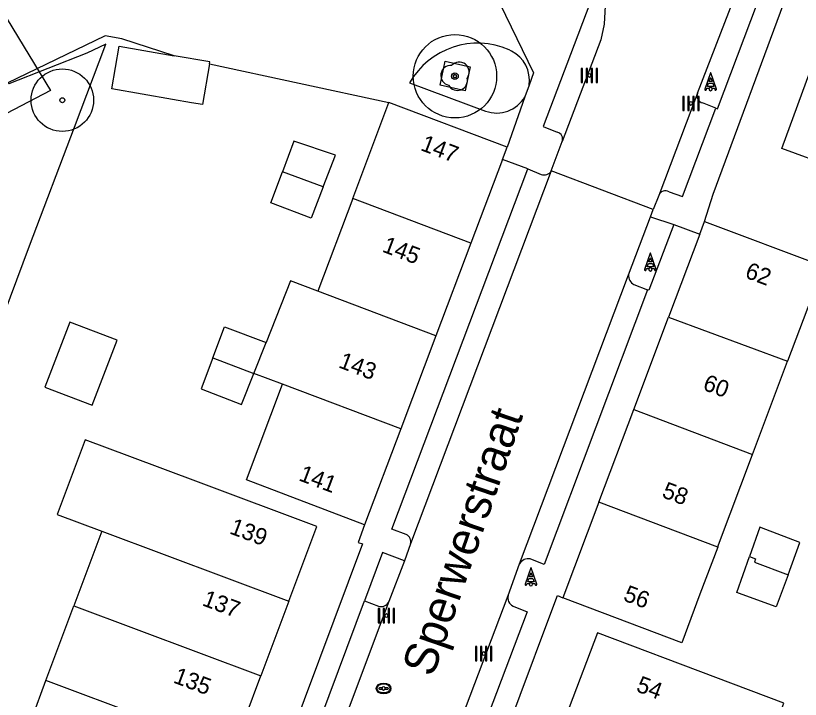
# Model space of a CAD drawing. Extents: x 192664 to 192925, y 446334 to 446521.
# Drawn here: x 192738.2 to 192785.27, y 446453.47 to 446494.45 of the extents above; entities that cross this region are included whole.
import ezdxf

# ---------------------------------------------------------------- set-up
doc = ezdxf.new("R2010")
doc.units = 0
for name, color, linetype in [('( Toegevoegd 29-11-2021 14_41_42) wegdeel vlak', 7, 'Continuous'), ('B-GV-GR-BOOM-S', 7, 'Continuous'), ('B-GV-KG-GRENS_WERKGRENS-G', 7, 'Continuous'), ('boom', 7, 'Continuous'), ('bovenleidingmast', 7, 'Continuous'), ('grens maaiveld', 7, 'Continuous'), ('huisnummerreeks BGT', 7, 'Continuous'), ('inspectie-   rioolput', 7, 'Continuous'), ('kant open verharding', 7, 'Continuous'), ('kant verharding', 7, 'Continuous'), ('kolk', 7, 'Continuous'), ('pand op maaiveld vlak', 7, 'Continuous'), ('straatnaam', 7, 'Continuous'), ('verkeerseiland - berm', 7, 'Continuous')]:
    doc.layers.add(name, color=color, linetype=linetype)

msp = doc.modelspace()

# ---------------------------------------------------------------- linework, layer by layer
at = {"layer": '( Toegevoegd 29-11-2021 14_41_42) wegdeel vlak'}
msp.add_line((192749.833, 446491.572), (192760.593, 446489.25), dxfattribs=at)
msp.add_lwpolyline([(192747.709, 446492.058), (192744.573, 446493.06), (192743.573, 446493.255), (192737.693, 446490.405)], dxfattribs=at)
at = {"layer": 'B-GV-GR-BOOM-S'}
for centre, radius in [((192764.55, 446490.826), 2.5), ((192740.997, 446489.39), 1.875), ((192764.55, 446490.826), 0.2), ((192740.997, 446489.39), 0.15)]:
    msp.add_circle(centre, radius, dxfattribs=at)
at = {"layer": 'B-GV-KG-GRENS_WERKGRENS-G'}
msp.add_lwpolyline([(192740.295, 446489.973), (192734.557, 446486.987), (192730.473, 446485.129), (192725.366, 446482.882), (192721.029, 446481.333), (192717.923, 446480.635), (192713.732, 446480.061), (192710.196, 446479.993), (192707.335, 446480.383), (192700.156, 446483.797), (192705.941, 446486.582), (192708.78, 446485.232), (192710.487, 446485), (192713.343, 446485.054), (192717.034, 446485.56), (192719.635, 446486.145), (192723.516, 446487.53), (192728.43, 446489.693), (192732.367, 446491.484), (192737.694, 446494.256)], close=True, dxfattribs=at)
at = {"layer": 'boom'}
msp.add_circle((192764.55, 446490.826), 0.1, dxfattribs=at)
for centre, radius, start, end in [((192764.3, 446490.876), 0.6, 85.137, 257.7544), ((192764.8, 446491.076), 0.6, 323.5446, 138.4658), ((192764.55, 446490.826), 0.1, 0, 180), ((192764.7, 446490.576), 0.6, 208.5058, 13.8356), ((192764.55, 446490.826), 0.1, 180, 0)]:
    msp.add_arc(centre, radius, start, end, dxfattribs=at)
at = {"layer": 'bovenleidingmast'}
for p, q in [((192779.881, 446491.025), (192779.54, 446490.052)), ((192780.24, 446490.052), (192779.899, 446491.025)), ((192776.265, 446480.215), (192775.924, 446479.242)), ((192776.624, 446479.242), (192776.283, 446480.215)), ((192769.099, 446461.346), (192768.758, 446460.373)), ((192769.458, 446460.373), (192769.117, 446461.346))]:
    msp.add_line(p, q, dxfattribs=at)
for points in [[(192779.899, 446490.722), (192779.977, 446490.502), (192779.803, 446490.502), (192779.881, 446490.722)], [(192779.634, 446490.019), (192779.663, 446490.102), (192779.803, 446490.102)], [(192779.977, 446490.102), (192780.117, 446490.102), (192780.146, 446490.019)], [(192776.283, 446479.912), (192776.361, 446479.692), (192776.187, 446479.692), (192776.265, 446479.912)], [(192776.018, 446479.209), (192776.047, 446479.292), (192776.187, 446479.292)], [(192776.361, 446479.292), (192776.501, 446479.292), (192776.53, 446479.209)], [(192769.117, 446461.043), (192769.195, 446460.823), (192769.021, 446460.823), (192769.099, 446461.043)], [(192768.852, 446460.34), (192768.881, 446460.423), (192769.021, 446460.423)], [(192769.195, 446460.423), (192769.335, 446460.423), (192769.364, 446460.34)]]:
    msp.add_lwpolyline(points, dxfattribs=at)
for points in [[(192780.012, 446490.402), (192780.082, 446490.202), (192779.698, 446490.202), (192779.768, 446490.402)], [(192776.396, 446479.592), (192776.466, 446479.392), (192776.082, 446479.392), (192776.152, 446479.592)], [(192769.23, 446460.723), (192769.3, 446460.523), (192768.916, 446460.523), (192768.986, 446460.723)]]:
    msp.add_lwpolyline(points, close=True, dxfattribs=at)
for centre, radius, start, end in [((192779.89, 446491.022), 0.01, 19.29, 160.71), ((192779.89, 446490.719), 0.01, 19.29, 160.71), ((192779.587, 446490.035), 0.05, 160.71, 340.71), ((192779.89, 446490.052), 0.1, 0, 180), ((192779.89, 446490.052), 0.1, 180, 0), ((192779.89, 446490.052), 0.1, 30, 150), ((192780.193, 446490.035), 0.05, 199.29, 19.29), ((192776.274, 446480.212), 0.01, 19.29, 160.71), ((192776.274, 446479.909), 0.01, 19.29, 160.71), ((192775.971, 446479.225), 0.05, 160.71, 340.71), ((192776.274, 446479.242), 0.1, 0, 180), ((192776.274, 446479.242), 0.1, 180, 0), ((192776.274, 446479.242), 0.1, 30, 150), ((192776.577, 446479.225), 0.05, 199.29, 19.29), ((192769.108, 446461.343), 0.01, 19.29, 160.71), ((192769.108, 446461.04), 0.01, 19.29, 160.71), ((192768.805, 446460.356), 0.05, 160.71, 340.71), ((192769.108, 446460.373), 0.1, 0, 180), ((192769.108, 446460.373), 0.1, 180, 0), ((192769.108, 446460.373), 0.1, 30, 150), ((192769.411, 446460.356), 0.05, 199.29, 19.29)]:
    msp.add_arc(centre, radius, start, end, dxfattribs=at)
at = {"layer": 'grens maaiveld'}
for p, q in [((192739.028, 446480.658), (192741.724, 446487.765)), ((192734.733, 446469.332), (192739.028, 446480.658))]:
    msp.add_line(p, q, dxfattribs=at)
msp.add_lwpolyline([(192741.724, 446487.765), (192743.611, 446492.741), (192742.468, 446492.211), (192737.789, 446490.36), (192737.693, 446490.405)], dxfattribs=at)
at = {"layer": 'inspectie-   rioolput'}
for p, q in [((192760.175, 446454.158), (192760.018, 446454.158)), ((192760.018, 446454.083), (192760.175, 446454.083)), ((192760.518, 446454.158), (192760.361, 446454.158)), ((192760.361, 446454.083), (192760.518, 446454.083))]:
    msp.add_line(p, q, dxfattribs=at)
for centre, radius, start, end in [((192760.268, 446454.12), 0.1, 0, 180), ((192760.018, 446454.12), 0.0375, 90, 270), ((192760.268, 446454.12), 0.1, 157.9757, 180), ((192760.268, 446454.12), 0.1, 180, 202.0243), ((192760.268, 446454.12), 0.1, 180, 0), ((192760.268, 446454.12), 0.1, 0, 22.0243), ((192760.268, 446454.12), 0.1, 337.9757, 0), ((192760.518, 446454.12), 0.0375, 270, 90)]:
    msp.add_arc(centre, radius, start, end, dxfattribs=at)
for major_axis, ratio in [((-0.442, 0), 0.73911), ((-0.392, 0), 0.689655)]:
    msp.add_ellipse((192760.268, 446454.12), major_axis=major_axis, ratio=ratio, dxfattribs=at)
at = {"layer": 'kant open verharding'}
for p, q in [((192768.751, 446489.598), (192767.686, 446486.569)), ((192770.332, 446485.145), (192770.985, 446486.905)), ((192768.919, 446485.267), (192767.41, 446485.838)), ((192776.448, 446482.826), (192770.332, 446485.145)), ((192776.776, 446483.684), (192776.448, 446482.826)), ((192777.672, 446481.946), (192779.24, 446481.355))]:
    msp.add_line(p, q, dxfattribs=at)
for points in [[(192779.53, 446482.124), (192780.051, 446483.746), (192784.415, 446495.597), (192785.528, 446497.018), (192791.864, 446500), (192801.451, 446504.762), (192802.996, 446505.531), (192810.052, 446508.944)], [(192765.561, 446498.667), (192769.255, 446491.03), (192768.995, 446490.291)], [(192759.131, 446463.938), (192758.744, 446462.881), (192758.998, 446462.784), (192748.571, 446434.902)], [(192761.515, 446461.771), (192760.208, 446462.264), (192759.133, 446459.368)], [(192763.131, 446439.452), (192770.245, 446458.483), (192770.698, 446459.694), (192771.023, 446459.551)]]:
    msp.add_lwpolyline(points, dxfattribs=at)
at = {"layer": 'kant verharding'}
for p, q in [((192779.096, 446489.802), (192776.776, 446483.684)), ((192768.919, 446485.267), (192769.718, 446484.933)), ((192770.332, 446485.145), (192761.884, 446462.784)), ((192776.287, 446482.406), (192776.448, 446482.826)), ((192768.431, 446461.589), (192774.955, 446478.925)), ((192761.884, 446462.784), (192761.515, 446461.771)), ((192761.515, 446461.771), (192760.585, 446459.343)), ((192767.733, 446459.699), (192768.431, 446461.589)), ((192759.42, 446437.63), (192767.733, 446459.699)), ((192751.413, 446438.852), (192759.133, 446459.368)), ((192760.585, 446459.343), (192752.554, 446437.93)), ((192759.133, 446459.368), (192759.958, 446459.051))]:
    msp.add_line(p, q, dxfattribs=at)
for points in [[(192777.392, 446483.905), (192778.209, 446483.619), (192780.204, 446488.916)], [(192761.621, 446463.349), (192760.755, 446463.677), (192768.919, 446485.267)], [(192776.11, 446478.029), (192769.909, 446461.548), (192769.066, 446461.885)], [(192768.035, 446459.06), (192768.878, 446458.723), (192760.872, 446437.554), (192760.052, 446437.884)]]:
    msp.add_lwpolyline(points, dxfattribs=at)
for centre, radius, start, end in [((192769.888, 446485.436), 0.531, 251.3114, 326.7858), ((192777.179, 446483.53), 0.431, 60.3638, 159.1088), ((192761.434, 446462.918), 0.47, 343.3869, 66.5358), ((192768.943, 446461.319), 0.579, 77.7905, 152.1938), ((192768.263, 446459.559), 0.548, 165.168, 245.4241), ((192760.116, 446459.532), 0.506, 251.8409, 338.1029)]:
    msp.add_arc(centre, radius, start, end, dxfattribs=at)
at = {"layer": 'kolk'}
for points in [[(192772.212, 446490.872), (192772.212, 446491.297), (192772.127, 446491.297), (192772.127, 446490.872), (192772.127, 446490.447), (192772.212, 446490.447)], [(192772.51, 446490.872), (192772.51, 446491.297), (192772.425, 446491.297), (192772.425, 446490.872), (192772.425, 446490.447), (192772.51, 446490.447)], [(192772.807, 446490.872), (192772.807, 446491.297), (192772.722, 446491.297), (192772.722, 446490.872), (192772.722, 446490.447), (192772.807, 446490.447)], [(192773.105, 446490.872), (192773.105, 446491.297), (192773.02, 446491.297), (192773.02, 446490.872), (192773.02, 446490.447), (192773.105, 446490.447)], [(192778.304, 446489.194), (192778.304, 446489.619), (192778.219, 446489.619), (192778.219, 446489.194), (192778.219, 446488.769), (192778.304, 446488.769)], [(192778.602, 446489.194), (192778.602, 446489.619), (192778.517, 446489.619), (192778.517, 446489.194), (192778.517, 446488.769), (192778.602, 446488.769)], [(192778.899, 446489.194), (192778.899, 446489.619), (192778.814, 446489.619), (192778.814, 446489.194), (192778.814, 446488.769), (192778.899, 446488.769)], [(192779.197, 446489.194), (192779.197, 446489.619), (192779.112, 446489.619), (192779.112, 446489.194), (192779.112, 446488.769), (192779.197, 446488.769)], [(192760.035, 446458.49), (192760.035, 446458.915), (192759.95, 446458.915), (192759.95, 446458.49), (192759.95, 446458.065), (192760.035, 446458.065)], [(192760.333, 446458.49), (192760.333, 446458.915), (192760.248, 446458.915), (192760.248, 446458.49), (192760.248, 446458.065), (192760.333, 446458.065)], [(192760.63, 446458.49), (192760.63, 446458.915), (192760.545, 446458.915), (192760.545, 446458.49), (192760.545, 446458.065), (192760.63, 446458.065)], [(192760.928, 446458.49), (192760.928, 446458.915), (192760.843, 446458.915), (192760.843, 446458.49), (192760.843, 446458.065), (192760.928, 446458.065)], [(192765.871, 446456.21), (192765.871, 446456.635), (192765.786, 446456.635), (192765.786, 446456.21), (192765.786, 446455.785), (192765.871, 446455.785)], [(192766.169, 446456.21), (192766.169, 446456.635), (192766.084, 446456.635), (192766.084, 446456.21), (192766.084, 446455.785), (192766.169, 446455.785)], [(192766.466, 446456.21), (192766.466, 446456.635), (192766.381, 446456.635), (192766.381, 446456.21), (192766.381, 446455.785), (192766.466, 446455.785)], [(192766.764, 446456.21), (192766.764, 446456.635), (192766.679, 446456.635), (192766.679, 446456.21), (192766.679, 446455.785), (192766.764, 446455.785)]]:
    msp.add_lwpolyline(points, close=True, dxfattribs=at)
for centre, start, end in [((192772.616, 446490.872), 0, 180), ((192772.616, 446490.872), 180, 0), ((192778.708, 446489.194), 0, 180), ((192778.708, 446489.194), 180, 0), ((192760.439, 446458.49), 0, 180), ((192760.439, 446458.49), 180, 0), ((192766.275, 446456.21), 0, 180), ((192766.275, 446456.21), 180, 0)]:
    msp.add_arc(centre, 0.1, start, end, dxfattribs=at)
at = {"layer": 'pand op maaiveld vlak'}
for p, q in [((192758.419, 446483.499), (192760.593, 446489.25)), ((192767.686, 446486.569), (192760.593, 446489.25)), ((192767.41, 446485.838), (192767.686, 446486.569)), ((192767.41, 446485.838), (192765.512, 446480.818)), ((192756.65, 446484.203), (192754.199, 446485.088)), ((192758.419, 446483.499), (192756.316, 446477.935)), ((192765.512, 446480.818), (192758.419, 446483.499)), ((192779.24, 446481.355), (192779.53, 446482.124)), ((192779.24, 446481.355), (192777.368, 446476.387)), ((192765.512, 446480.818), (192763.408, 446475.254)), ((192763.408, 446475.254), (192756.316, 446477.935)), ((192775.276, 446470.838), (192777.368, 446476.387)), ((192777.368, 446476.387), (192784.508, 446473.734)), ((192763.408, 446475.254), (192761.305, 446469.689)), ((192752.483, 446473.013), (192753.216, 446474.855)), ((192750.024, 446473.942), (192752.483, 446473.013)), ((192782.404, 446468.151), (192784.508, 446473.734)), ((192754.212, 446472.371), (192752.483, 446473.013)), ((192761.305, 446469.689), (192754.212, 446472.371)), ((192773.185, 446465.288), (192775.276, 446470.838)), ((192775.276, 446470.838), (192782.404, 446468.151)), ((192761.305, 446469.689), (192759.131, 446463.938)), ((192773.185, 446465.288), (192771.023, 446459.551)), ((192780.312, 446462.601), (192773.185, 446465.288)), ((192743.37, 446463.554), (192741.693, 446459.079)), ((192743.37, 446463.554), (192754.588, 446459.35)), ((192740.015, 446454.605), (192741.693, 446459.079)), ((192741.693, 446459.079), (192752.91, 446454.875)), ((192754.588, 446459.35), (192752.91, 446454.875)), ((192751.233, 446450.4), (192752.91, 446454.875)), ((192738.338, 446450.129), (192740.015, 446454.605)), ((192751.233, 446450.4), (192740.015, 446454.605))]:
    msp.add_line(p, q, dxfattribs=at)
for points in [[(192792.525, 446489.271), (192789.784, 446481.79), (192786.371, 446483.041), (192787.224, 446485.369), (192784.159, 446486.492), (192787.037, 446494.347)], [(192749.833, 446491.572), (192749.408, 446489.125), (192748.749, 446489.239), (192747.607, 446489.431), (192743.964, 446490.063), (192744.41, 446492.631), (192747.709, 446492.058)], [(192749.833, 446491.572), (192749.853, 446491.686), (192747.709, 446492.058)], [(192756.65, 446484.203), (192757.379, 446486.084), (192754.888, 446486.941), (192754.199, 446485.088)], [(192756.65, 446484.203), (192755.92, 446482.321), (192753.509, 446483.234), (192754.199, 446485.088)], [(192779.53, 446482.124), (192786.658, 446479.438), (192784.508, 446473.734)], [(192756.316, 446477.935), (192754.686, 446478.551), (192753.216, 446474.855)], [(192741.448, 446476.082), (192739.954, 446472.185), (192742.788, 446471.099), (192744.281, 446474.996), (192741.448, 446476.082)], [(192750.024, 446473.942), (192750.726, 446475.796), (192753.216, 446474.855)], [(192750.024, 446473.942), (192749.322, 446472.087), (192751.743, 446471.155), (192752.483, 446473.013)], [(192759.131, 446463.938), (192752.038, 446466.619), (192754.212, 446472.371)], [(192754.588, 446459.35), (192756.265, 446463.825), (192749.17, 446466.484), (192745.047, 446468.029), (192742.362, 446469.035), (192740.685, 446464.56), (192743.37, 446463.554)], [(192780.312, 446462.601), (192780.361, 446462.73), (192782.404, 446468.151)], [(192784.536, 446460.939), (192785.243, 446462.87), (192783.2, 446463.643), (192782.832, 446463.782), (192782.213, 446462.032)], [(192780.312, 446462.601), (192779.249, 446459.77), (192778.154, 446456.864), (192771.023, 446459.551)], [(192784.536, 446460.939), (192783.829, 446459.007), (192781.783, 446459.755), (192781.451, 446459.876), (192782.213, 446462.032)], [(192782.213, 446462.032), (192782.588, 446461.891), (192782.515, 446461.7), (192784.536, 446460.939)], [(192782.591, 446448.755), (192784.284, 446453.247), (192780.202, 446454.786), (192773.094, 446457.465), (192771.4, 446452.974)]]:
    msp.add_lwpolyline(points, dxfattribs=at)
at = {"layer": 'verkeerseiland - berm'}
for p, q in [((192779.096, 446489.802), (192782.127, 446497.618)), ((192767.944, 446492.335), (192767.801, 446492.408)), ((192761.828, 446490.429), (192766.384, 446488.738)), ((192768.995, 446490.291), (192768.751, 446489.598)), ((192780.204, 446488.916), (192779.398, 446489.226)), ((192774.955, 446478.925), (192776.287, 446482.406)), ((192776.287, 446482.406), (192777.672, 446481.946)), ((192775.288, 446478.335), (192776.11, 446478.029))]:
    msp.add_line(p, q, dxfattribs=at)
for points in [[(192780.204, 446488.916), (192780.3, 446488.879), (192783.494, 446497.368), (192782.261, 446497.894)], [(192773.367, 446497.097), (192771.694, 446492.7), (192769.851, 446487.804), (192770.692, 446487.472)], [(192773.367, 446497.097), (192773.526, 446496.058), (192773.566, 446495.048), (192773.494, 446493.942), (192773.307, 446493.007), (192770.985, 446486.905)], [(192763.963, 446491.728), (192765.459, 446491.398), (192765.155, 446489.951), (192763.659, 446490.281), (192763.963, 446491.728)], [(192777.672, 446481.946), (192776.178, 446478.004), (192776.11, 446478.029)]]:
    msp.add_lwpolyline(points, dxfattribs=at)
for centre, radius, start, end in [((192765.91, 446488.113), 4.693, 66.2315, 150.431), ((192767.055, 446490.586), 1.963, 351.3683, 63.0551), ((192767.053, 446490.585), 1.964, 250.1006, 329.8345), ((192779.513, 446489.654), 0.443, 160.4181, 254.9184), ((192770.578, 446487.054), 0.433, 339.8875, 74.7682), ((192775.623, 446478.913), 0.668, 178.9813, 239.9001)]:
    msp.add_arc(centre, radius, start, end, dxfattribs=at)

# ---------------------------------------------------------------- texts
at = {"layer": 'huisnummerreeks BGT'}
for s, rotation, p in [('147', 339.3, (192762.431, 446486.407)), ('145', 339.3, (192760.132, 446480.321)), ('62', 339.4, (192781.892, 446478.771)), ('143', 339.3, (192757.51, 446473.385)), ('60', 339.4, (192779.362, 446472.05)), ('141', 339.3, (192755.123, 446466.612)), ('58', 339.4, (192776.911, 446465.605)), ('139', 339.5, (192750.968, 446463.428)), ('137', 339.5, (192749.332, 446459.119)), ('56', 339.4, (192774.595, 446459.411)), ('135', 339.5, (192747.597, 446454.487)), ('54', 339.4, (192775.363, 446453.968))]:
    msp.add_text(s, height=1, rotation=rotation, dxfattribs=at).set_placement(p)
at = {"layer": 'straatnaam'}
msp.add_text('Sperwerstraat', height=2, rotation=71, dxfattribs=at).set_placement((192763.228, 446454.747))

doc.saveas('drawing.dxf')
